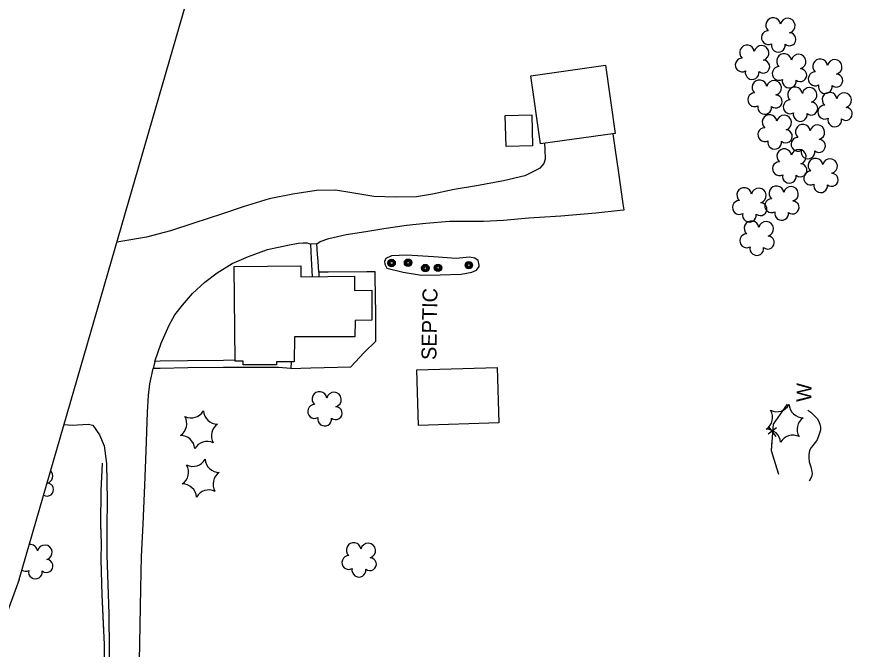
# Model space of a CAD drawing. Extents: x 353423 to 364002, y 127000 to 201942.
# Drawn here: x 357759 to 358095.3, y 132554.6 to 132809.4 of the extents above; entities that cross this region are included whole.
import ezdxf

# ---------------------------------------------------------------- set-up
doc = ezdxf.new("R2010")
doc.units = 0
for name, color, linetype in [('E_DTM_SlopeBottom', 7, 'Continuous'), ('E_FEN_Generic', 7, 'Continuous'), ('E_MISCPROP', 7, 'Continuous'), ('E_RDWY_Gravel', 7, 'Continuous'), ('E_STRUCT_WingWall', 7, 'Continuous'), ('E_UTL_ETransformer', 7, 'Continuous'), ('E_WTR_FlowLine', 7, 'Continuous')]:
    doc.layers.add(name, color=color, linetype=linetype)

msp = doc.modelspace()

# ---------------------------------------------------------------- linework, layer by layer
at = {"layer": 'E_DTM_SlopeBottom'}
for p, q in [((358064.85, 132643.84), (358061.49, 132641.27)), ((358061.63, 132644.23), (358064.6, 132640.3))]:
    msp.add_line(p, q, dxfattribs=at)
for points in [[(358069.14, 132653.42), (358063.45, 132645.35), (358062.71, 132634.65), (358065.68, 132625.11)], [(358069.14, 132653.42), (358063.45, 132645.35), (358063.44, 132645.27)], [(358077.41, 132650.88), (358078.69, 132650.08), (358079.39, 132649.45), (358080.04, 132648.82), (358081.32, 132647.44), (358081.96, 132646.02), (358082.25, 132645.35), (358082.53, 132644.11), (358082.55, 132642.86), (358082.04, 132641.21), (358081.23, 132638.97), (358080.47, 132637.86), (358079.5, 132636.71), (358078.74, 132635.89), (358078.15, 132634.73), (358077.88, 132632.99), (358077.83, 132631.71), (358078.02, 132630.09), (358078.7, 132628.09), (358079.1, 132626.26), (358079.21, 132625.47), (358078.95, 132624.14), (358077.93, 132622.33)], [(358062.99, 132638.7), (358062.71, 132634.65), (358064.87, 132627.72)], [(358064.87, 132627.72), (358065.68, 132625.11)]]:
    msp.add_lwpolyline(points, dxfattribs=at)
at = {"layer": 'E_FEN_Generic'}
for centre, radius, start, end in [((358063.51, 132806), 2.97, 7.4434, 228.6773), ((358069.36, 132805.79), 2.97, 285.0942, 168.0675), ((358061.56, 132800.99), 2.78, 90.4143, 298.1873), ((358070.03, 132800.31), 2.61, 229.7995, 87.7321), ((358052.97, 132795), 2.97, 7.4434, 228.6773), ((358058.82, 132794.78), 2.97, 285.0942, 168.0675), ((358065.59, 132797.92), 2.78, 167.0913, 8.1024), ((358067.88, 132791.56), 2.97, 7.4434, 228.6773), ((358073.73, 132791.35), 2.97, 285.0942, 168.0675), ((358051.03, 132789.99), 2.78, 90.4143, 298.1873), ((358059.49, 132789.3), 2.61, 229.7995, 87.7321), ((358082.38, 132789.37), 2.97, 7.4434, 228.6773), ((358088.23, 132789.16), 2.97, 285.0942, 168.0675), ((358055.05, 132786.92), 2.78, 167.0913, 8.1024), ((358065.93, 132786.55), 2.78, 90.4143, 298.1873), ((358074.4, 132785.86), 2.61, 229.7995, 87.7321), ((358080.43, 132784.36), 2.78, 90.4143, 298.1873), ((358058.01, 132780.96), 2.97, 7.4434, 228.6773), ((358063.86, 132780.74), 2.97, 285.0942, 168.0675), ((358069.96, 132783.48), 2.78, 167.0913, 8.1024), ((358088.9, 132783.67), 2.61, 229.7995, 87.7321), ((358072.3, 132778.1), 2.97, 7.4434, 228.6773), ((358078.15, 132777.89), 2.97, 285.0942, 168.0675), ((358084.46, 132781.29), 2.78, 167.0913, 8.1024), ((358056.07, 132775.95), 2.78, 90.4143, 298.1873), ((358064.53, 132775.26), 2.61, 229.7995, 87.7321), ((358086.22, 132775.96), 2.97, 7.4434, 228.6773), ((358092.07, 132775.75), 2.97, 285.0942, 168.0675), ((358060.09, 132772.88), 2.78, 167.0913, 8.1024), ((358070.35, 132773.09), 2.78, 90.4143, 298.1873), ((358078.82, 132772.41), 2.61, 229.7995, 87.7321), ((358084.27, 132770.95), 2.78, 90.4143, 298.1873), ((358062.05, 132766.93), 2.97, 7.4434, 228.6773), ((358074.38, 132770.03), 2.78, 167.0913, 8.1024), ((358092.74, 132770.27), 2.61, 229.7995, 87.7321), ((358067.9, 132766.72), 2.97, 285.0942, 168.0675), ((358088.3, 132767.88), 2.78, 167.0913, 8.1024), ((358060.11, 132761.92), 2.78, 90.4143, 298.1873), ((358068.57, 132761.23), 2.61, 229.7995, 87.7321), ((358075.41, 132763.05), 2.97, 7.4434, 228.6773), ((358081.26, 132762.84), 2.97, 285.0942, 168.0675), ((358073.47, 132758.04), 2.78, 90.4143, 298.1873), ((358081.93, 132757.36), 2.61, 229.7995, 87.7321), ((358064.13, 132758.85), 2.78, 167.0913, 8.1024), ((358067.96, 132753.21), 2.97, 7.4434, 228.6773), ((358073.81, 132753), 2.97, 285.0942, 168.0675), ((358077.49, 132754.97), 2.78, 167.0913, 8.1024), ((358066.02, 132748.2), 2.78, 90.4143, 298.1873), ((358074.48, 132747.52), 2.61, 229.7995, 87.7321), ((358080.54, 132749.42), 2.97, 7.4434, 228.6773), ((358086.39, 132749.21), 2.97, 285.0942, 168.0675), ((358078.59, 132744.41), 2.78, 90.4143, 298.1873), ((358087.06, 132743.73), 2.61, 229.7995, 87.7321), ((358070.04, 132745.13), 2.78, 167.0913, 8.1024), ((358051.86, 132737.57), 2.97, 7.4434, 228.6773), ((358057.71, 132737.36), 2.97, 285.0942, 168.0675), ((358064.81, 132738.26), 2.97, 7.4434, 228.6773), ((358070.66, 132738.05), 2.97, 285.0942, 168.0675), ((358082.62, 132741.34), 2.78, 167.0913, 8.1024), ((358049.91, 132732.56), 2.78, 90.4143, 298.1873), ((358058.38, 132731.88), 2.61, 229.7995, 87.7321), ((358062.87, 132733.25), 2.78, 90.4143, 298.1873), ((358071.33, 132732.57), 2.61, 229.7995, 87.7321), ((358053.94, 132729.49), 2.78, 167.0913, 8.1024), ((358066.89, 132730.18), 2.78, 167.0913, 8.1024), ((358054.82, 132724.14), 2.97, 7.4434, 228.6773), ((358060.68, 132723.92), 2.97, 285.0942, 168.0675), ((358052.88, 132719.13), 2.78, 90.4143, 298.1873), ((358061.35, 132718.44), 2.61, 229.7995, 87.7321), ((358056.91, 132716.06), 2.78, 167.0913, 8.1024), ((357880.87, 132655.42), 2.97, 7.4434, 228.6773), ((357886.72, 132655.21), 2.97, 285.0942, 168.0675), ((357878.92, 132650.41), 2.78, 90.4143, 298.1873), ((357887.39, 132649.73), 2.61, 229.7995, 87.7321), ((358064.98, 132656.04), 5.72, 244.2311, 329.996), ((358075.64, 132653.6), 5.72, 184.2311, 269.996), ((357829.19, 132653.52), 5.72, 244.2311, 329.996), ((357839.86, 132651.08), 5.72, 184.2311, 269.996), ((358057.53, 132648.03), 5.72, 304.2311, 29.996), ((357821.75, 132645.5), 5.72, 304.2311, 29.996), ((357843.08, 132640.62), 5.72, 124.2311, 209.996), ((357882.95, 132647.34), 2.78, 167.0913, 8.1024), ((358078.86, 132643.15), 5.72, 124.2311, 209.996), ((358060.75, 132637.57), 5.72, 4.2311, 89.996), ((357824.97, 132635.04), 5.72, 4.2311, 89.996), ((358071.42, 132635.13), 5.72, 64.2311, 149.996), ((357835.63, 132632.6), 5.72, 64.2311, 149.996), ((357822.45, 132625.99), 5.72, 304.2311, 29.996), ((357829.9, 132634.01), 5.72, 244.2311, 329.996), ((357840.56, 132631.57), 5.72, 184.2311, 269.996), ((357770.57, 132624.43), 2.97, 285.0942, 44.1745), ((357843.78, 132621.11), 5.72, 124.2311, 209.996), ((357771.24, 132618.95), 2.61, 238.4646, 87.7321), ((357825.67, 132615.53), 5.72, 4.2311, 89.996), ((357836.34, 132613.09), 5.72, 64.2311, 149.996), ((357764.47, 132593.85), 2.97, 7.4434, 96.8648), ((357770.32, 132593.64), 2.97, 285.0942, 168.0675), ((357894.65, 132594.6), 2.97, 7.4434, 228.6773), ((357900.5, 132594.39), 2.97, 285.0942, 168.0675), ((357892.71, 132589.59), 2.78, 90.4143, 298.1873), ((357901.18, 132588.91), 2.61, 229.7995, 87.7321), ((357770.99, 132588.16), 2.61, 229.7995, 87.7321), ((357762.53, 132588.84), 2.78, 239.5628, 298.1873), ((357766.55, 132585.77), 2.78, 167.0913, 8.1024), ((357896.73, 132586.52), 2.78, 167.0913, 8.1024)]:
    msp.add_arc(centre, radius, start, end, dxfattribs=at)
at = {"layer": 'E_MISCPROP'}
for points in [[(357879.79, 132717.91), (357881.21, 132718.89), (357884.67, 132720.02), (357891.61, 132721.64), (357899.6, 132722.84), (357906.83, 132724.09), (357915.85, 132725.45), (357923.74, 132726.28), (357933.17, 132727.05), (357940.19, 132727.1), (357946.91, 132727.11), (357955.01, 132727.43), (357965.14, 132728.45), (357978.06, 132729.22), (357992.18, 132730.44), (358001.94, 132731.53), (358003.48, 132731.6), (358003.17, 132734.05), (358001.44, 132746.56), (357999.93, 132756.58), (357999.12, 132762.29)], [(357971.44, 132758.36), (357971.58, 132756.1), (357971.75, 132752.07), (357971.23, 132750.29), (357969.63, 132748.44), (357968.13, 132747.63), (357963.5, 132745.35), (357954.97, 132743.33), (357944.03, 132741.25), (357935.1, 132739.85), (357926.36, 132737.95), (357920, 132736.9), (357911.45, 132736.7), (357902.82, 132737.04), (357893.87, 132738.42), (357887.33, 132739.49), (357879.73, 132739.41), (357870.09, 132737.98), (357860.69, 132736), (357850.2, 132732.88), (357841.91, 132730.06), (357830.25, 132726.29), (357820.88, 132723.11), (357811.26, 132720.56), (357800.91, 132718.84), (357799.34, 132718.61)], [(357814.66, 132670.55), (357817.19, 132677.96), (357820.34, 132685.23), (357822.63, 132689.27), (357825.74, 132693.22), (357829.82, 132697.91), (357834.68, 132702.46), (357839.74, 132706.27), (357845.67, 132710.02), (357852.35, 132712.81), (357860.01, 132715.63), (357868.21, 132717.41), (357872.24, 132718.2), (357874.32, 132718.34), (357875.93, 132718.33), (357877.3, 132717.73)], [(357880.58, 132706.57), (357880.29, 132710.96), (357880.12, 132713.76), (357879.79, 132717.91), (357877.3, 132717.73), (357877.53, 132711.88), (357877.93, 132704.71)], [(357869.47, 132670.46), (357869.41, 132667.77), (357877.43, 132667.97), (357893.53, 132668.34), (357898.86, 132674.21), (357903.56, 132678.69), (357903.55, 132689.64), (357903.3, 132704.83), (357903.28, 132706.7), (357901.66, 132706.64), (357899.88, 132706.7), (357884.44, 132706.57), (357880.58, 132706.57), (357880.61, 132704.73)], [(357846.88, 132671.01), (357842.26, 132671), (357827.79, 132670.83), (357816.7, 132670.62), (357814.66, 132670.55), (357813.89, 132667.74)], [(357809.21, 132591.98), (357809.89, 132605.08), (357810.6, 132620.72), (357811.07, 132634.41), (357811.62, 132650.09), (357812.02, 132656.81), (357812.65, 132661.58), (357813.89, 132667.74)], [(357869.41, 132667.77), (357864.4, 132668.15), (357852.32, 132668.12), (357842.28, 132668.1), (357827.83, 132667.92), (357816.71, 132667.71), (357813.89, 132667.74)], [(357778.1, 132645.18), (357781.4, 132644.93), (357787.83, 132645.24), (357789.7, 132644.89), (357792.31, 132640.96), (357794.17, 132636.58), (357795.13, 132629.43), (357795.39, 132614.74), (357795.23, 132603.91), (357795.22, 132592.54)], [(357795.22, 132592.54), (357796.03, 132568.93), (357796.38, 132539.66), (357797.1, 132509.53), (357797.57, 132485.24), (357797.74, 132466.39), (357797.86, 132446.66), (357797.45, 132424.37), (357796.99, 132407.23), (357796.9, 132388.55), (357796.41, 132367.2), (357795.99, 132349.21), (357795.94, 132329.77), (357795.69, 132312.71), (357795.29, 132303.19), (357794.53, 132297.75), (357793.53, 132294.69), (357791.64, 132291.73), (357789.28, 132289.19), (357786.92, 132287), (357785.64, 132285.52)], [(357823.16, 132285.51), (357818.92, 132287.97), (357815.41, 132291.1), (357813.17, 132293.66), (357811.11, 132296.87), (357809.44, 132300.75), (357808.23, 132304.89), (357807.63, 132309.65), (357807.58, 132315.78), (357807.94, 132330.54), (357807.69, 132355.94), (357807.44, 132381.04), (357807.98, 132409.07), (357808.42, 132436.2), (357808.09, 132456.24), (357807.93, 132475.64), (357808.02, 132495.29), (357807.72, 132518.95), (357808.14, 132536.64), (357808.54, 132556.93), (357808.95, 132579.17), (357809.21, 132591.98)]]:
    msp.add_lwpolyline(points, dxfattribs=at)
at = {"layer": 'E_RDWY_Gravel'}
for points in [[(357760.04, 132582.69), (357843.81, 132872.41), (357849.63, 133227.58), (357838.39, 133502.56)], [(357760.04, 132582.69), (357720.49, 132474.74), (357667.63, 132475.52), (357546.15, 132477.04), (357427.86, 132479.38), (357370.89, 132480.79), (357285.54, 132482.71), (357215.13, 132481.98), (357125.35, 132482.44), (357001.13, 132483.13), (356876.96, 132484.17), (356873.17, 132284.46)]]:
    msp.add_lwpolyline(points, dxfattribs=at)
at = {"layer": 'E_STRUCT_WingWall'}
for points in [[(357793.37, 132629.58), (357792.92, 132618.5), (357792.74, 132605.1), (357793.07, 132597.21), (357792.82, 132590.75)], [(357793.37, 132629.58), (357792.92, 132618.5), (357792.74, 132605.1), (357792.92, 132600.59)], [(357793.04, 132596.6), (357792.97, 132594.6)], [(357792.82, 132590.75), (357793.31, 132576.58), (357794.24, 132556.62), (357794.35, 132542.07)], [(357792.82, 132590.75), (357793.31, 132576.58), (357794, 132561.77)], [(357794.18, 132557.78), (357794.24, 132556.62), (357794.24, 132555.78)]]:
    msp.add_lwpolyline(points, dxfattribs=at)
at = {"layer": 'E_UTL_ETransformer'}
for centre, radius in [((357909.9, 132710.22), 1.5), ((357909.91, 132710.22), 1.22), ((357909.92, 132710.22), 0.968), ((357909.93, 132710.19), 0.605), ((357916.55, 132710.31), 1.5), ((357916.55, 132710.32), 1.22), ((357916.56, 132710.31), 0.968), ((357916.57, 132710.28), 0.605), ((357923.49, 132708.16), 1.5), ((357923.5, 132708.17), 1.22), ((357928.6, 132708.28), 1.5), ((357928.6, 132708.28), 1.22), ((357928.61, 132708.27), 0.968), ((357940.98, 132709.35), 1.5), ((357940.98, 132709.35), 1.22), ((357940.99, 132709.34), 0.968), ((357941, 132709.32), 0.605), ((357923.51, 132708.16), 0.968), ((357923.52, 132708.13), 0.605), ((357928.62, 132708.25), 0.605)]:
    msp.add_circle(centre, radius, dxfattribs=at)
at = {"layer": 'E_WTR_FlowLine'}
for points in [[(357995.99, 132789.83), (357999.89, 132762.4), (357969.88, 132758.14), (357965.99, 132785.57)], [(357966.35, 132769.9), (357966.67, 132757.44), (357955.97, 132757.17), (357955.65, 132769.62)], [(357908.02, 132708.13), (357914.53, 132706.49), (357921.92, 132705.34), (357929.5, 132705.38), (357937.88, 132705.72), (357942.27, 132706.49), (357944.12, 132707.37), (357945.14, 132708.78), (357945.22, 132709.3), (357944.79, 132711.23), (357943.48, 132712.16), (357941.29, 132712.53), (357935.92, 132712.04), (357926.73, 132712.67), (357916.03, 132713.3), (357909.84, 132713.05), (357907.54, 132712.02), (357907.05, 132710.86), (357907.16, 132709.69)], [(357846.89, 132670.67), (357846.55, 132708.81), (357873.32, 132709.05), (357873.36, 132704.67), (357894.93, 132704.86), (357894.98, 132699.19), (357901.89, 132699.25), (357902, 132687.25), (357902, 132687.25), (357895.2, 132687.08), (357895.17, 132680.44), (357870.77, 132680.5), (357870.75, 132670.46), (357863.61, 132670.47), (357863.61, 132669.16), (357850.23, 132669.19), (357850.23, 132670.7)], [(357920.1, 132667.14), (357952.39, 132668.17), (357953.1, 132645.83), (357920.8, 132644.81)]]:
    msp.add_lwpolyline(points, close=True, dxfattribs=at)

# ---------------------------------------------------------------- texts
at = {"layer": 'E_DTM_SlopeBottom'}
msp.add_text('W', height=6, rotation=89.0214, dxfattribs=at).set_placement((358078.84, 132654.2))
at = {"layer": 'E_UTL_ETransformer'}
msp.add_text('SEPTIC', height=6, rotation=89.0198, dxfattribs=at).set_placement((357927.91, 132671.11))

doc.saveas('drawing.dxf')
